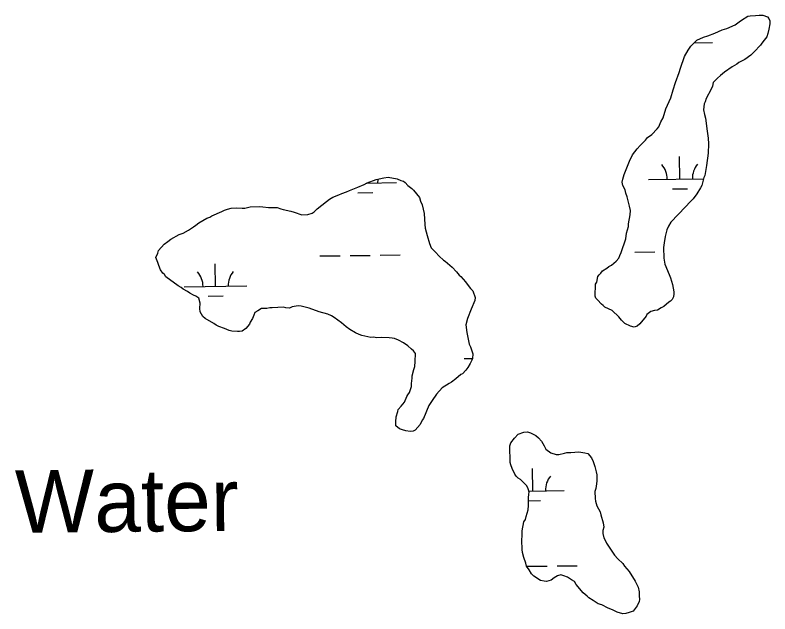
# Model space of a CAD drawing. Extents: x 3702978 to 3741108, y 397120 to 422907.
# Drawn here: x 3711433 to 3712636, y 403784 to 404739 of the extents above; entities that cross this region are included whole.
import ezdxf

# ---------------------------------------------------------------- set-up
doc = ezdxf.new("R2010")
doc.units = 0
for name, color, linetype in [('V-RIVR-IDEN', 7, 'Continuous'), ('V-TOPO-SHOR', 7, 'Continuous'), ('V-WETL-SWMP', 7, 'Continuous')]:
    doc.layers.add(name, color=color, linetype=linetype)

msp = doc.modelspace()

# ---------------------------------------------------------------- linework, layer by layer
at = {"layer": 'V-TOPO-SHOR'}
for points in [[(3712486.205, 404631.699), (3712492.055, 404647.478), (3712493.976, 404654.327), (3712500.458, 404672.844), (3712506.406, 404683.173), (3712510.384, 404689.378), (3712519.75, 404699.087), (3712530.565, 404704.051), (3712537.341, 404706.217), (3712548.849, 404710.513), (3712560.345, 404715.49), (3712567.802, 404717.668), (3712581.329, 404723.363), (3712587.375, 404728.242), (3712591.414, 404731.04), (3712601.523, 404737.355), (3712604.917, 404738.097), (3712613.773, 404738.256), (3712619.211, 404739.035), (3712625.343, 404739.146), (3712632.885, 404736.555), (3712634.978, 404733.867), (3712636.414, 404729.804), (3712636.5, 404725.035), (3712634.603, 404716.823), (3712633.362, 404709.986), (3712631.416, 404704.499), (3712627.427, 404698.975), (3712623.425, 404694.133), (3712621.43, 404691.371), (3712611.407, 404680.288), (3712606.042, 404675.421), (3712596.627, 404668.437), (3712587.175, 404663.497), (3712583.817, 404660.711), (3712576.397, 404656.489), (3712564.281, 404648.093), (3712557.566, 404642.521), (3712552.871, 404638.348), (3712546.18, 404631.413), (3712544.916, 404625.938), (3712542.957, 404621.133), (3712535.051, 404605.998), (3712533.105, 404600.511)], [(3712533.105, 404600.511), (3712531.792, 404597.762), (3712530.601, 404588.199), (3712532.098, 404580.73), (3712533.57, 404574.623), (3712535.08, 404566.472), (3712535.92, 404557.628), (3712538.233, 404542.677), (3712538.392, 404533.821), (3712537.98, 404518.821), (3712535.609, 404499.015), (3712532.484, 404483.285), (3712531.183, 404479.854), (3712527.997, 404467.53), (3712526.026, 404463.406), (3712520.066, 404453.758), (3712514.069, 404446.154), (3712509.386, 404441.3), (3712502.039, 404432.99), (3712478.623, 404408.717), (3712474.645, 404402.513), (3712472.03, 404396.332), (3712469.489, 404386.064), (3712467.629, 404375.809), (3712467.082, 404368.303), (3712467.388, 404351.271), (3712468.921, 404341.758), (3712476.028, 404325.53), (3712478.169, 404320.116), (3712481.09, 404309.265), (3712483.342, 404297.72), (3712483.403, 404294.314), (3712482.807, 404289.533), (3712480.837, 404285.409), (3712478.161, 404282.635), (3712475.46, 404281.223), (3712467.407, 404274.264), (3712463.356, 404272.147), (3712457.286, 404268.63), (3712452.53, 404267.863), (3712446.423, 404266.391), (3712440.377, 404261.512), (3712439.063, 404258.762), (3712429.065, 404246.316), (3712425.038, 404242.836), (3712420.294, 404241.388), (3712414.138, 404242.641), (3712405.196, 404247.25), (3712399.648, 404252.603), (3712395.462, 404257.979), (3712385.06, 404268.015), (3712378.88, 404270.63), (3712373.381, 404273.257), (3712370.607, 404275.933), (3712367.845, 404277.928), (3712361.591, 404284.631), (3712358.817, 404287.307), (3712358.075, 404290.701), (3712358.414, 404309.788), (3712360.396, 404313.231), (3712362.281, 404322.125), (3712364.276, 404324.886), (3712366.952, 404327.66), (3712369.616, 404331.116), (3712376.355, 404335.325), (3712379.712, 404338.112), (3712383.763, 404340.229), (3712391.147, 404346.495), (3712395.83, 404351.349), (3712397.12, 404355.461), (3712399.078, 404360.267), (3712406.861, 404382.214), (3712408.065, 404391.095), (3712411.276, 404402.056), (3712411.202, 404406.144), (3712413.67, 404420.499), (3712414.229, 404427.324), (3712412.744, 404434.112), (3712409.069, 404449.039), (3712406.915, 404455.134), (3712405.455, 404460.559), (3712401.926, 404467.311), (3712401.147, 404472.749), (3712401.743, 404477.53), (3712404.333, 404485.073), (3712412.81, 404506.351), (3712417.408, 404515.974), (3712424.731, 404525.647), (3712429.402, 404531.182), (3712432.078, 404533.956), (3712438.111, 404539.516), (3712441.444, 404543.665), (3712448.171, 404548.556), (3712456.869, 404557.572), (3712459.533, 404561.027), (3712462.804, 404568.582), (3712466.088, 404575.456), (3712470.6, 404589.848), (3712478.47, 404607.027), (3712482.325, 404620.044), (3712486.205, 404631.699)], [(3711711.261, 404295.443), (3711707.806, 404298.107), (3711700.92, 404302.072), (3711697.465, 404304.736), (3711692.647, 404307.375), (3711673.315, 404321.339), (3711671.198, 404325.39), (3711668.436, 404327.385), (3711664.932, 404332.774), (3711662.084, 404339.538), (3711660.636, 404344.282), (3711657.083, 404352.396), (3711660.367, 404359.27), (3711661.656, 404363.382), (3711670.329, 404373.76), (3711676.387, 404377.958), (3711681.095, 404381.45), (3711694.586, 404389.188), (3711700.68, 404391.342), (3711709.451, 404396.27), (3711717.541, 404401.186), (3711720.898, 404403.972), (3711725.606, 404407.464), (3711738.415, 404415.19), (3711743.16, 404416.638), (3711746.529, 404418.743), (3711762.757, 404425.849), (3711766.808, 404427.967), (3711771.552, 404429.415), (3711777.659, 404430.887), (3711785.141, 404431.703), (3711794.691, 404431.193), (3711799.46, 404431.279), (3711807.598, 404433.469), (3711822.586, 404433.739), (3711828.048, 404433.155), (3711836.929, 404431.952), (3711850.555, 404432.196), (3711856.723, 404430.263), (3711860.154, 404428.961), (3711872.465, 404426.456), (3711877.952, 404424.51), (3711890.288, 404420.643), (3711899.826, 404420.814), (3711906.602, 404422.98), (3711909.971, 404425.085), (3711914.655, 404429.94), (3711929.435, 404441.79), (3711934.142, 404445.282), (3711939.531, 404448.786), (3711949.008, 404452.364), (3711953.74, 404454.493), (3711961.185, 404457.353), (3711965.917, 404459.482), (3711979.457, 404464.496), (3711989.602, 404468.767), (3711994.322, 404471.578), (3712008.543, 404476.603), (3712020.757, 404479.549), (3712027.557, 404480.352), (3712041.913, 404477.884), (3712048.093, 404475.269), (3712052.205, 404473.98), (3712054.967, 404471.985), (3712059.14, 404467.29), (3712065.357, 404462.631), (3712068.131, 404459.955), (3712077.889, 404447.863), (3712079.349, 404442.438), (3712082.185, 404436.355), (3712085.154, 404422.779), (3712086.154, 404405.078), (3712086.945, 404398.959), (3712089.878, 404387.426), (3712093.517, 404374.544), (3712096.364, 404367.78), (3712103.299, 404361.09), (3712108.871, 404354.375), (3712115.794, 404348.366), (3712118.556, 404346.371), (3712129.627, 404337.029), (3712136.575, 404329.657), (3712140.76, 404324.281), (3712143.522, 404322.286), (3712151.175, 404313.564), (3712155.372, 404307.506), (3712158.864, 404302.798), (3712163.013, 404299.465), (3712166.615, 404288.626), (3712166.019, 404283.845), (3712160.133, 404270.11), (3712154.27, 404255.012), (3712151.729, 404244.744), (3712153.312, 404232.506), (3712157.048, 404214.173), (3712159.165, 404210.122), (3712162.78, 404198.601), (3712162.233, 404191.095), (3712160.919, 404188.346), (3712158.28, 404183.528), (3712154.996, 404176.654)], [(3712154.996, 404176.654), (3712151.663, 404172.505), (3712146.311, 404166.957), (3712143.61, 404165.546), (3712135.557, 404158.587), (3712128.83, 404153.695), (3712124.779, 404151.578), (3712114.001, 404144.57), (3712104.647, 404134.18), (3712098.006, 404124.52), (3712092.702, 404116.247), (3712084.213, 404095.65), (3712082.218, 404092.888), (3712078.934, 404086.014), (3712070.918, 404077.011), (3712067.536, 404075.587), (3712062.779, 404074.82), (3712055.942, 404076.06), (3712050.468, 404077.325), (3712045.662, 404079.283), (3712040.126, 404083.954), (3712040.016, 404090.086), (3712040.551, 404098.273), (3712043.129, 404106.497), (3712043.749, 404109.916), (3712048.42, 404115.451), (3712051.096, 404118.225), (3712053.76, 404121.681), (3712057.689, 404130.611), (3712059.002, 404133.36), (3712061.666, 404136.815), (3712064.901, 404146.414), (3712064.816, 404151.183), (3712066.019, 404160.064), (3712065.958, 404163.47), (3712068.5, 404173.738), (3712070.458, 404178.544), (3712070.992, 404186.731), (3712071.453, 404199.006), (3712067.961, 404203.714), (3712065.188, 404206.39), (3712058.958, 404211.73), (3712052.06, 404216.376), (3712044.493, 404220.329), (3712037.631, 404222.932), (3712034.213, 404223.552), (3712029.431, 404224.148), (3712017.157, 404224.609), (3712008.981, 404224.462), (3712004.882, 404225.07), (3712000.113, 404224.984), (3711985.745, 404228.134), (3711981.633, 404229.423), (3711975.453, 404232.038), (3711966.498, 404237.329), (3711960.963, 404242), (3711953.359, 404247.997), (3711941.618, 404256.645), (3711937.482, 404259.297), (3711931.301, 404261.912), (3711917.603, 404265.755), (3711901.823, 404271.605), (3711888.818, 404274.779), (3711884.037, 404275.375), (3711874.524, 404273.841), (3711870.473, 404271.724), (3711864.329, 404272.295), (3711860.911, 404272.915), (3711842.529, 404271.903), (3711839.123, 404271.842), (3711834.366, 404271.075), (3711825.51, 404270.916), (3711820.121, 404267.412), (3711815.401, 404264.602), (3711813.43, 404260.477), (3711811.484, 404254.99), (3711807.495, 404249.467), (3711806.875, 404246.048), (3711800.865, 404239.126), (3711794.807, 404234.928), (3711790.732, 404234.173), (3711787.326, 404234.112), (3711778.457, 404234.634), (3711774.345, 404235.924), (3711766.79, 404239.195), (3711757.872, 404242.443), (3711753.748, 404244.413), (3711749.612, 404247.065), (3711735.84, 404254.995), (3711732.372, 404258.34), (3711728.15, 404265.761), (3711727.371, 404271.199), (3711727.905, 404279.386), (3711725.715, 404287.525), (3711720.885, 404290.845), (3711717.454, 404292.147), (3711711.261, 404295.443)], [(3712308.732, 404040.392), (3712312.807, 404041.146), (3712318.939, 404041.256), (3712331.87, 404042.17), (3712341.432, 404040.979), (3712346.226, 404039.702), (3712351.798, 404032.987), (3712354.633, 404026.905), (3712357.505, 404018.778), (3712359.696, 404010.64), (3712360.463, 404005.883), (3712360.646, 403995.664), (3712359.43, 403987.465), (3712358.81, 403984.046), (3712357.533, 403979.253), (3712357.741, 403967.671), (3712358.496, 403963.596), (3712360.674, 403956.139), (3712365.614, 403946.687), (3712367.063, 403941.942), (3712370.701, 403929.059), (3712371.505, 403922.259), (3712370.24, 403916.785), (3712370.326, 403912.016), (3712371.811, 403905.227), (3712374.646, 403899.145), (3712376.057, 403896.444), (3712386.558, 403880.959), (3712388.663, 403877.589), (3712394.223, 403871.556), (3712401.851, 403864.196), (3712404.65, 403860.158), (3712412.303, 403851.436), (3712421.44, 403835.926), (3712426.38, 403826.474), (3712427.878, 403819.004), (3712427.988, 403812.873), (3712428.779, 403806.754), (3712428.159, 403803.335), (3712424.875, 403796.461), (3712418.209, 403788.164), (3712412.114, 403786.01), (3712406.689, 403784.55), (3712401.932, 403783.783), (3712393.027, 403786.349), (3712385.459, 403790.302), (3712378.598, 403792.904), (3712368.281, 403798.171), (3712362.794, 403800.117), (3712354.521, 403805.42), (3712347.635, 403809.386), (3712344.861, 403812.062), (3712338.632, 403817.402), (3712327.487, 403830.831), (3712324.676, 403835.551), (3712319.859, 403838.191), (3712313.654, 403842.168), (3712308.155, 403844.795), (3712303.361, 403846.072), (3712297.936, 403844.612), (3712292.547, 403841.108), (3712287.839, 403837.616), (3712280.382, 403835.437), (3712276.282, 403836.045), (3712270.808, 403837.31), (3712259.785, 403843.927), (3712256.305, 403847.953), (3712252.789, 403854.024), (3712248.591, 403860.082), (3712247.143, 403864.826), (3712244.259, 403873.633), (3712242.068, 403881.772), (3712241.302, 403886.529), (3712241.032, 403901.516), (3712241.579, 403909.023), (3712241.445, 403916.516), (3712243.913, 403930.872), (3712246.577, 403934.327), (3712247.854, 403939.12), (3712251.064, 403950.082), (3712251.623, 403956.907), (3712251.403, 403969.17), (3712251.986, 403974.632), (3712252.606, 403978.05), (3712251.146, 403983.476), (3712249.017, 403988.208), (3712238.614, 403998.244), (3712235.171, 404000.226), (3712231.704, 404003.571), (3712229.599, 404006.941), (3712225.352, 404015.724), (3712223.198, 404021.819), (3712222.456, 404025.213), (3712221.979, 404051.782), (3712223.256, 404056.576), (3712229.253, 404064.18), (3712235.274, 404070.421), (3712244.069, 404073.986), (3712250.201, 404074.096), (3712254.994, 404072.82), (3712263.255, 404068.197)], [(3712263.255, 404068.197), (3712267.403, 404064.865), (3712272.27, 404059.5), (3712276.492, 404052.08), (3712279.315, 404046.678), (3712286.919, 404040.682), (3712295.824, 404038.115), (3712299.912, 404038.189), (3712308.732, 404040.392)]]:
    msp.add_lwpolyline(points, dxfattribs=at)
at = {"layer": 'V-WETL-SWMP'}
for p, q in [((3712515.762, 404694.952), (3712544.735, 404695.312)), ((3712492.845, 404477.408), (3712492.398, 404513.405)), ((3712442.849, 404476.787), (3712530.672, 404477.878)), ((3711993.7, 404471.208), (3712040.972, 404471.795)), ((3711979.169, 404455.595), (3712003.167, 404455.893)), ((3712481.038, 404461.829), (3712505.036, 404462.127)), ((3711967.004, 404355.435), (3711999.001, 404355.833)), ((3712015, 404356.031), (3712046.998, 404356.429)), ((3712420.877, 404361.073), (3712452.874, 404361.471)), ((3711919.008, 404354.839), (3711951.005, 404355.236)), ((3711752.533, 404306.337), (3711752.086, 404342.334)), ((3711702.537, 404305.716), (3711802.529, 404306.958)), ((3711740.726, 404290.758), (3711764.724, 404291.056)), ((3712149.058, 404191.183), (3712162.251, 404191.347)), ((3712258.535, 403979.922), (3712258.088, 404015.919)), ((3712252.124, 403979.843), (3712308.531, 403980.543)), ((3712251.489, 403964.403), (3712270.726, 403964.641)), ((3712249.183, 403859.726), (3712281.181, 403860.123)), ((3712297.179, 403860.322), (3712329.177, 403860.72))]:
    msp.add_line(p, q, dxfattribs=at)
for points in [[(3712486.205, 404631.699), (3712492.055, 404647.478), (3712493.976, 404654.327), (3712500.458, 404672.844), (3712506.406, 404683.173), (3712510.384, 404689.378), (3712519.75, 404699.087), (3712530.565, 404704.051), (3712537.341, 404706.217), (3712548.849, 404710.513), (3712560.345, 404715.49), (3712567.802, 404717.668), (3712581.329, 404723.363), (3712587.375, 404728.242), (3712591.414, 404731.04), (3712601.523, 404737.355), (3712604.917, 404738.097), (3712613.773, 404738.256), (3712619.211, 404739.035), (3712625.343, 404739.146), (3712632.885, 404736.555), (3712634.978, 404733.867), (3712636.414, 404729.804), (3712636.5, 404725.035), (3712634.603, 404716.823), (3712633.362, 404709.986), (3712631.416, 404704.499), (3712627.427, 404698.975), (3712623.425, 404694.133), (3712621.43, 404691.371), (3712611.407, 404680.288), (3712606.042, 404675.421), (3712596.627, 404668.437), (3712587.175, 404663.497), (3712583.817, 404660.711), (3712576.397, 404656.489), (3712564.281, 404648.093), (3712557.566, 404642.521), (3712552.871, 404638.348), (3712546.18, 404631.413), (3712544.916, 404625.938), (3712542.957, 404621.133), (3712535.051, 404605.998), (3712533.105, 404600.511)], [(3712533.105, 404600.511), (3712531.792, 404597.762), (3712530.601, 404588.199), (3712532.098, 404580.73), (3712533.57, 404574.623), (3712535.08, 404566.472), (3712535.92, 404557.628), (3712538.233, 404542.677), (3712538.392, 404533.821), (3712537.98, 404518.821), (3712535.609, 404499.015), (3712532.484, 404483.285), (3712531.183, 404479.854), (3712527.997, 404467.53), (3712526.026, 404463.406), (3712520.066, 404453.758), (3712514.069, 404446.154), (3712509.386, 404441.3), (3712502.039, 404432.99), (3712478.623, 404408.717), (3712474.645, 404402.513), (3712472.03, 404396.332), (3712469.489, 404386.064), (3712467.629, 404375.809), (3712467.082, 404368.303), (3712467.388, 404351.271), (3712468.921, 404341.758), (3712476.028, 404325.53), (3712478.169, 404320.116), (3712481.09, 404309.265), (3712483.342, 404297.72), (3712483.403, 404294.314), (3712482.807, 404289.533), (3712480.837, 404285.409), (3712478.161, 404282.635), (3712475.46, 404281.223), (3712467.407, 404274.264), (3712463.356, 404272.147), (3712457.286, 404268.63), (3712452.53, 404267.863), (3712446.423, 404266.391), (3712440.377, 404261.512), (3712439.063, 404258.762), (3712429.065, 404246.316), (3712425.038, 404242.836), (3712420.294, 404241.388), (3712414.138, 404242.641), (3712405.196, 404247.25), (3712399.648, 404252.603), (3712395.462, 404257.979), (3712385.06, 404268.015), (3712378.88, 404270.63), (3712373.381, 404273.257), (3712370.607, 404275.933), (3712367.845, 404277.928), (3712361.591, 404284.631), (3712358.817, 404287.307), (3712358.075, 404290.701), (3712358.414, 404309.788), (3712360.396, 404313.231), (3712362.281, 404322.125), (3712364.276, 404324.886), (3712366.952, 404327.66), (3712369.616, 404331.116), (3712376.355, 404335.325), (3712379.712, 404338.112), (3712383.763, 404340.229), (3712391.147, 404346.495), (3712395.83, 404351.349), (3712397.12, 404355.461), (3712399.078, 404360.267), (3712406.861, 404382.214), (3712408.065, 404391.095), (3712411.276, 404402.056), (3712411.202, 404406.144), (3712413.67, 404420.499), (3712414.229, 404427.324), (3712412.744, 404434.112), (3712409.069, 404449.039), (3712406.915, 404455.134), (3712405.455, 404460.559), (3712401.926, 404467.311), (3712401.147, 404472.749), (3712401.743, 404477.53), (3712404.333, 404485.073), (3712412.81, 404506.351), (3712417.408, 404515.974), (3712424.731, 404525.647), (3712429.402, 404531.182), (3712432.078, 404533.956), (3712438.111, 404539.516), (3712441.444, 404543.665), (3712448.171, 404548.556), (3712456.869, 404557.572), (3712459.533, 404561.027), (3712462.804, 404568.582), (3712466.088, 404575.456), (3712470.6, 404589.848), (3712478.47, 404607.027), (3712482.325, 404620.044), (3712486.205, 404631.699)], [(3711711.261, 404295.443), (3711707.806, 404298.107), (3711700.92, 404302.072), (3711697.465, 404304.736), (3711692.647, 404307.375), (3711673.315, 404321.339), (3711671.198, 404325.39), (3711668.436, 404327.385), (3711664.932, 404332.774), (3711662.084, 404339.538), (3711660.636, 404344.282), (3711657.083, 404352.396), (3711660.367, 404359.27), (3711661.656, 404363.382), (3711670.329, 404373.76), (3711676.387, 404377.958), (3711681.095, 404381.45), (3711694.586, 404389.188), (3711700.68, 404391.342), (3711709.451, 404396.27), (3711717.541, 404401.186), (3711720.898, 404403.972), (3711725.606, 404407.464), (3711738.415, 404415.19), (3711743.16, 404416.638), (3711746.529, 404418.743), (3711762.757, 404425.849), (3711766.808, 404427.967), (3711771.552, 404429.415), (3711777.659, 404430.887), (3711785.141, 404431.703), (3711794.691, 404431.193), (3711799.46, 404431.279), (3711807.598, 404433.469), (3711822.586, 404433.739), (3711828.048, 404433.155), (3711836.929, 404431.952), (3711850.555, 404432.196), (3711856.723, 404430.263), (3711860.154, 404428.961), (3711872.465, 404426.456), (3711877.952, 404424.51), (3711890.288, 404420.643), (3711899.826, 404420.814), (3711906.602, 404422.98), (3711909.971, 404425.085), (3711914.655, 404429.94), (3711929.435, 404441.79), (3711934.142, 404445.282), (3711939.531, 404448.786), (3711949.008, 404452.364), (3711953.74, 404454.493), (3711961.185, 404457.353), (3711965.917, 404459.482), (3711979.457, 404464.496), (3711989.602, 404468.767), (3711994.322, 404471.578), (3712008.543, 404476.603), (3712020.757, 404479.549), (3712027.557, 404480.352), (3712041.913, 404477.884), (3712048.093, 404475.269), (3712052.205, 404473.98), (3712054.967, 404471.985), (3712059.14, 404467.29), (3712065.357, 404462.631), (3712068.131, 404459.955), (3712077.889, 404447.863), (3712079.349, 404442.438), (3712082.185, 404436.355), (3712085.154, 404422.779), (3712086.154, 404405.078), (3712086.945, 404398.959), (3712089.878, 404387.426), (3712093.517, 404374.544), (3712096.364, 404367.78), (3712103.299, 404361.09), (3712108.871, 404354.375), (3712115.794, 404348.366), (3712118.556, 404346.371), (3712129.627, 404337.029), (3712136.575, 404329.657), (3712140.76, 404324.281), (3712143.522, 404322.286), (3712151.175, 404313.564), (3712155.372, 404307.506), (3712158.864, 404302.798), (3712163.013, 404299.465), (3712166.615, 404288.626), (3712166.019, 404283.845), (3712160.133, 404270.11), (3712154.27, 404255.012), (3712151.729, 404244.744), (3712153.312, 404232.506), (3712157.048, 404214.173), (3712159.165, 404210.122), (3712162.78, 404198.601), (3712162.233, 404191.095), (3712160.919, 404188.346), (3712158.28, 404183.528), (3712154.996, 404176.654)], [(3712154.996, 404176.654), (3712151.663, 404172.505), (3712146.311, 404166.957), (3712143.61, 404165.546), (3712135.557, 404158.587), (3712128.83, 404153.695), (3712124.779, 404151.578), (3712114.001, 404144.57), (3712104.647, 404134.18), (3712098.006, 404124.52), (3712092.702, 404116.247), (3712084.213, 404095.65), (3712082.218, 404092.888), (3712078.934, 404086.014), (3712070.918, 404077.011), (3712067.536, 404075.587), (3712062.779, 404074.82), (3712055.942, 404076.06), (3712050.468, 404077.325), (3712045.662, 404079.283), (3712040.126, 404083.954), (3712040.016, 404090.086), (3712040.551, 404098.273), (3712043.129, 404106.497), (3712043.749, 404109.916), (3712048.42, 404115.451), (3712051.096, 404118.225), (3712053.76, 404121.681), (3712057.689, 404130.611), (3712059.002, 404133.36), (3712061.666, 404136.815), (3712064.901, 404146.414), (3712064.816, 404151.183), (3712066.019, 404160.064), (3712065.958, 404163.47), (3712068.5, 404173.738), (3712070.458, 404178.544), (3712070.992, 404186.731), (3712071.453, 404199.006), (3712067.961, 404203.714), (3712065.188, 404206.39), (3712058.958, 404211.73), (3712052.06, 404216.376), (3712044.493, 404220.329), (3712037.631, 404222.932), (3712034.213, 404223.552), (3712029.431, 404224.148), (3712017.157, 404224.609), (3712008.981, 404224.462), (3712004.882, 404225.07), (3712000.113, 404224.984), (3711985.745, 404228.134), (3711981.633, 404229.423), (3711975.453, 404232.038), (3711966.498, 404237.329), (3711960.963, 404242), (3711953.359, 404247.997), (3711941.618, 404256.645), (3711937.482, 404259.297), (3711931.301, 404261.912), (3711917.603, 404265.755), (3711901.823, 404271.605), (3711888.818, 404274.779), (3711884.037, 404275.375), (3711874.524, 404273.841), (3711870.473, 404271.724), (3711864.329, 404272.295), (3711860.911, 404272.915), (3711842.529, 404271.903), (3711839.123, 404271.842), (3711834.366, 404271.075), (3711825.51, 404270.916), (3711820.121, 404267.412), (3711815.401, 404264.602), (3711813.43, 404260.477), (3711811.484, 404254.99), (3711807.495, 404249.467), (3711806.875, 404246.048), (3711800.865, 404239.126), (3711794.807, 404234.928), (3711790.732, 404234.173), (3711787.326, 404234.112), (3711778.457, 404234.634), (3711774.345, 404235.924), (3711766.79, 404239.195), (3711757.872, 404242.443), (3711753.748, 404244.413), (3711749.612, 404247.065), (3711735.84, 404254.995), (3711732.372, 404258.34), (3711728.15, 404265.761), (3711727.371, 404271.199), (3711727.905, 404279.386), (3711725.715, 404287.525), (3711720.885, 404290.845), (3711717.454, 404292.147), (3711711.261, 404295.443)], [(3712308.732, 404040.392), (3712312.807, 404041.146), (3712318.939, 404041.256), (3712331.87, 404042.17), (3712341.432, 404040.979), (3712346.226, 404039.702), (3712351.798, 404032.987), (3712354.633, 404026.905), (3712357.505, 404018.778), (3712359.696, 404010.64), (3712360.463, 404005.883), (3712360.646, 403995.664), (3712359.43, 403987.465), (3712358.81, 403984.046), (3712357.533, 403979.253), (3712357.741, 403967.671), (3712358.496, 403963.596), (3712360.674, 403956.139), (3712365.614, 403946.687), (3712367.063, 403941.942), (3712370.701, 403929.059), (3712371.505, 403922.259), (3712370.24, 403916.785), (3712370.326, 403912.016), (3712371.811, 403905.227), (3712374.646, 403899.145), (3712376.057, 403896.444), (3712386.558, 403880.959), (3712388.663, 403877.589), (3712394.223, 403871.556), (3712401.851, 403864.196), (3712404.65, 403860.158), (3712412.303, 403851.436), (3712421.44, 403835.926), (3712426.38, 403826.474), (3712427.878, 403819.004), (3712427.988, 403812.873), (3712428.779, 403806.754), (3712428.159, 403803.335), (3712424.875, 403796.461), (3712418.209, 403788.164), (3712412.114, 403786.01), (3712406.689, 403784.55), (3712401.932, 403783.783), (3712393.027, 403786.349), (3712385.459, 403790.302), (3712378.598, 403792.904), (3712368.281, 403798.171), (3712362.794, 403800.117), (3712354.521, 403805.42), (3712347.635, 403809.386), (3712344.861, 403812.062), (3712338.632, 403817.402), (3712327.487, 403830.831), (3712324.676, 403835.551), (3712319.859, 403838.191), (3712313.654, 403842.168), (3712308.155, 403844.795), (3712303.361, 403846.072), (3712297.936, 403844.612), (3712292.547, 403841.108), (3712287.839, 403837.616), (3712280.382, 403835.437), (3712276.282, 403836.045), (3712270.808, 403837.31), (3712259.785, 403843.927), (3712256.305, 403847.953), (3712252.789, 403854.024), (3712248.591, 403860.082), (3712247.143, 403864.826), (3712244.259, 403873.633), (3712242.068, 403881.772), (3712241.302, 403886.529), (3712241.032, 403901.516), (3712241.579, 403909.023), (3712241.445, 403916.516), (3712243.913, 403930.872), (3712246.577, 403934.327), (3712247.854, 403939.12), (3712251.064, 403950.082), (3712251.623, 403956.907), (3712251.403, 403969.17), (3712251.986, 403974.632), (3712252.606, 403978.05), (3712251.146, 403983.476), (3712249.017, 403988.208), (3712238.614, 403998.244), (3712235.171, 404000.226), (3712231.704, 404003.571), (3712229.599, 404006.941), (3712225.352, 404015.724), (3712223.198, 404021.819), (3712222.456, 404025.213), (3712221.979, 404051.782), (3712223.256, 404056.576), (3712229.253, 404064.18), (3712235.274, 404070.421), (3712244.069, 404073.986), (3712250.201, 404074.096), (3712254.994, 404072.82), (3712263.255, 404068.197)], [(3712263.255, 404068.197), (3712267.403, 404064.865), (3712272.27, 404059.5), (3712276.492, 404052.08), (3712279.315, 404046.678), (3712286.919, 404040.682), (3712295.824, 404038.115), (3712299.912, 404038.189), (3712308.732, 404040.392)]]:
    msp.add_lwpolyline(points, dxfattribs=at)
for centre, start, end in [((3712437.601, 404477.197), 359.939883, 41.483542), ((3712548.078, 404478.569), 139.93988, 181.483539), ((3712046.209, 404472.335), 171.950137, 181.483539), ((3711697.289, 404306.126), 359.939883, 41.483542), ((3711807.766, 404307.498), 139.93988, 181.483539), ((3712313.768, 403981.083), 139.93988, 181.483539)]:
    msp.add_arc(centre, 35.246, start, end, dxfattribs=at)

# ---------------------------------------------------------------- texts
at = {"layer": 'V-RIVR-IDEN'}
msp.add_text('Water', height=99.9998, rotation=0.572928, dxfattribs=at).set_placement((3711433.259, 403912.958))

doc.saveas('drawing.dxf')
